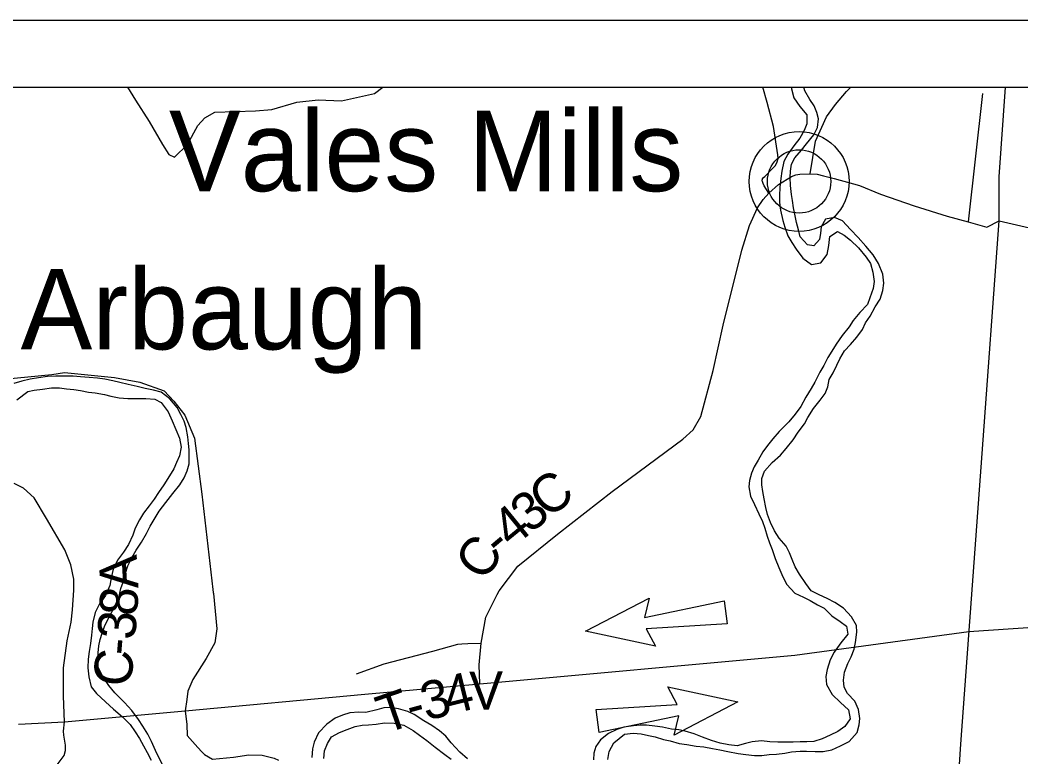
# Model space of a CAD drawing. Extents: x -15 to 405, y -40 to 87.
# Drawn here: x 26.107 to 27.6, y -28.194 to -27.096 of the extents above; entities that cross this region are included whole.
import ezdxf

# ---------------------------------------------------------------- set-up
doc = ezdxf.new("R2010")
doc.units = 0
for name, color, linetype in [('GM_P_State_Location', 7, 'Continuous'), ('GM_X_Major_Lake_Text', 7, 'Continuous'), ('GM_X_Minor_Lake', 7, 'Continuous'), ('GM_X_Minor_River', 7, 'Continuous'), ('GM_X_Rail_Line', 7, 'Continuous'), ('GM_X_State_Location', 7, 'Continuous'), ('GM_X_Township', 7, 'Continuous'), ('GM_X_Township_Road', 7, 'Continuous'), ('GM_X_Township_ROW', 7, 'Continuous'), ('GM_X_Township_Subdivision_Text', 7, 'Continuous'), ('GM_X_Township_Text', 7, 'Continuous')]:
    doc.layers.add(name, color=color, linetype=linetype)

msp = doc.modelspace()

# ---------------------------------------------------------------- linework, layer by layer
at = {"layer": 'GM_P_State_Location'}
for points in [[(26.2674, -27.1955), (26.2795, -27.2151), (26.2997, -27.2469), (26.3196, -27.2809), (26.3291, -27.2961), (26.3374, -27.2998), (26.3567, -27.2808), (26.3725, -27.2527), (26.3827, -27.2413), (26.3975, -27.233), (26.4581, -27.2306), (26.4827, -27.229), (26.5198, -27.2179), (26.5517, -27.2144), (26.5865, -27.2158), (26.6358, -27.2051), (26.6482, -27.1955)], [(27.5424, -27.2051), (27.521, -27.3963)], [(26.6091, -28.0702), (26.65, -28.055), (26.7227, -28.0362), (26.7602, -28.0259), (26.766, -28.0254)], [(26.766, -28.0254), (26.7661, -28.0254), (26.775, -28.0247), (26.7949, -28.0243)], [(26.3533, -28.1249), (26.3559, -28.1456), (26.3563, -28.1619), (26.3723, -28.1797), (26.3782, -28.186), (26.3783, -28.1861)], [(26.3783, -28.1861), (26.3821, -28.1901), (26.394, -28.1971), (26.4255, -28.1944), (26.4482, -28.1908), (26.4683, -28.1911), (26.4863, -28.1956), (26.4927, -28.1984)]]:
    msp.add_lwpolyline(points, dxfattribs=at)
at = {"layer": 'GM_X_Major_Lake_Text'}
msp.add_lwpolyline([(27.2854, -27.3245), (27.2931, -27.2763), (27.3097, -27.2399), (27.3229, -27.2216), (27.3395, -27.2018), (27.3458, -27.1955)], dxfattribs=at)
at = {"layer": 'GM_X_Rail_Line'}
for p, q in [((27.567, -27.3293), (27.5764, -27.1955)), ((27.567, -27.3948), (27.567, -27.3293)), ((27.5416, -27.7418), (27.567, -27.3948)), ((27.5098, -28.1749), (27.5416, -27.7418)), ((27.4737, -28.7166), (27.5098, -28.1749))]:
    msp.add_line(p, q, dxfattribs=at)
at = {"layer": 'GM_X_State_Location'}
for p, q in [((26.9502, -28.0065), (27.0452, -27.9573)), ((27.0452, -27.9573), (27.0384, -27.9858)), ((27.0384, -27.9858), (27.157, -27.9613)), ((27.157, -27.9613), (27.1616, -27.9954)), ((27.1616, -27.9954), (27.0406, -28.0031)), ((27.0548, -28.0289), (26.9502, -28.0065)), ((27.0406, -28.0031), (27.0548, -28.0289)), ((27.0869, -28.1155), (27.0729, -28.0895)), ((27.0729, -28.0895), (27.1775, -28.1118)), ((26.966, -28.1231), (27.0869, -28.1155)), ((27.1775, -28.1118), (27.0825, -28.1612)), ((26.9706, -28.1573), (26.966, -28.1231)), ((27.0893, -28.1327), (26.9706, -28.1573)), ((27.0825, -28.1612), (27.0893, -28.1327))]:
    msp.add_line(p, q, dxfattribs=at)
for points in [[(27.5221, -28.0069), (27.794, -27.9884), (27.8248, -27.9846), (27.9313, -27.9711), (28.0014, -27.9502), (28.0572, -27.9216), (28.1015, -27.8881), (28.1837, -27.8185), (28.3618, -27.6615), (28.4315, -27.6071), (28.5024, -27.5572), (28.767, -27.3945)], [(26.1048, -28.1452), (26.1735, -28.1414), (26.3533, -28.1249), (26.6213, -28.1005), (26.793, -28.0849), (27.2624, -28.0421), (27.5221, -28.0069)]]:
    msp.add_lwpolyline(points, dxfattribs=at)
at = {"layer": 'GM_X_Township'}
for p, q in [((23.0652, -27.0955), (30.0652, -27.0955)), ((23.1652, -27.1955), (29.9652, -27.1955))]:
    msp.add_line(p, q, dxfattribs=at)
at = {"layer": 'GM_X_Township_Road'}
for points in [[(27.2571, -27.1955), (27.2574, -27.1982), (27.2608, -27.2115), (27.2699, -27.2244), (27.2802, -27.2369), (27.2802, -27.2502), (27.2764, -27.2604), (27.2699, -27.2714), (27.2608, -27.2828), (27.252, -27.2953), (27.2463, -27.3063), (27.2429, -27.3207), (27.2414, -27.3317)], [(27.2577, -27.3553), (27.2562, -27.342), (27.2554, -27.3302), (27.2558, -27.3207), (27.2577, -27.3105), (27.2623, -27.301), (27.2725, -27.2896), (27.2798, -27.2801), (27.2908, -27.2665), (27.2961, -27.2555), (27.298, -27.2426), (27.2954, -27.2331), (27.2912, -27.2236), (27.2848, -27.2141), (27.2776, -27.2008), (27.2761, -27.1955)], [(27.2414, -27.3317), (27.2402, -27.3446), (27.2398, -27.3575), (27.2398, -27.3674), (27.2409, -27.3788), (27.2447, -27.3943), (27.2477, -27.4042), (27.2519, -27.4171), (27.258, -27.427), (27.2644, -27.4368), (27.2746, -27.4505), (27.2875, -27.46), (27.3012, -27.4574), (27.3107, -27.4452), (27.313, -27.4316), (27.3145, -27.4183), (27.3263, -27.4107), (27.3358, -27.4164), (27.3457, -27.4236), (27.3574, -27.435), (27.3688, -27.4487), (27.3753, -27.4586), (27.3787, -27.4715), (27.3809, -27.4851), (27.3794, -27.4957), (27.3741, -27.5094), (27.3706, -27.5196), (27.3596, -27.5314), (27.3493, -27.5435), (27.3433, -27.553), (27.333, -27.5659), (27.3243, -27.5784), (27.3178, -27.589), (27.3117, -27.5985), (27.3056, -27.6103), (27.2999, -27.6205), (27.2923, -27.6353), (27.2866, -27.6448), (27.279, -27.6577), (27.2714, -27.6713), (27.263, -27.6827), (27.2535, -27.6945), (27.2391, -27.7089), (27.2299, -27.7195), (27.2216, -27.7297), (27.2147, -27.7392), (27.2079, -27.7517), (27.2018, -27.7616), (27.198, -27.7711), (27.1949, -27.7817), (27.1938, -27.7912), (27.1964, -27.8052), (27.2021, -27.8178), (27.2086, -27.8314), (27.2142, -27.8428), (27.2176, -27.8527), (27.2214, -27.8648), (27.2248, -27.8747), (27.2286, -27.8849), (27.2332, -27.8982), (27.2385, -27.9115), (27.2445, -27.9256), (27.2506, -27.937), (27.2627, -27.9495), (27.2756, -27.9556), (27.2855, -27.9605), (27.2965, -27.967), (27.306, -27.9723), (27.3178, -27.9837), (27.3299, -27.992), (27.3394, -27.9989), (27.3413, -28.011), (27.331, -28.0239), (27.3211, -28.0376), (27.315, -28.0493), (27.3105, -28.0634), (27.3089, -28.074), (27.3097, -28.0861), (27.318, -28.1009), (27.3305, -28.1127), (27.3423, -28.1237), (27.3449, -28.137), (27.3369, -28.1484), (27.3267, -28.156), (27.3153, -28.1616), (27.3031, -28.1666), (27.2906, -28.1707), (27.2803, -28.1711), (27.2705, -28.1715), (27.2602, -28.1719), (27.2371, -28.1718), (27.2253, -28.1711), (27.2128, -28.1699), (27.1991, -28.1714), (27.1888, -28.1737), (27.1767, -28.1771), (27.1642, -28.1756), (27.1512, -28.1733), (27.138, -28.1691), (27.1247, -28.1645), (27.1125, -28.1596)], [(27.1395, -28.1813), (27.1505, -28.1832), (27.1626, -28.1858), (27.1782, -28.1889), (27.1892, -28.1904), (27.2021, -28.1915), (27.2131, -28.1919), (27.2241, -28.1904), (27.2351, -28.1897), (27.2477, -28.1882), (27.2576, -28.1863), (27.2705, -28.1851), (27.28, -28.1852), (27.2929, -28.1859), (27.3046, -28.1855), (27.3175, -28.1833), (27.3308, -28.1772), (27.3434, -28.1708), (27.3552, -28.1575), (27.3582, -28.1461), (27.3594, -28.1363), (27.3575, -28.1233), (27.3518, -28.1108), (27.3408, -28.0994), (27.3359, -28.0899), (27.3351, -28.0793), (27.3363, -28.0676), (27.3416, -28.0547), (27.3465, -28.0444), (27.3507, -28.0334), (27.353, -28.0232), (27.3549, -28.008), (27.3546, -27.9977), (27.347, -27.9848), (27.3352, -27.9723), (27.322, -27.9636), (27.3109, -27.9575), (27.2988, -27.9522), (27.2867, -27.9461), (27.2787, -27.9355), (27.2696, -27.9214), (27.2631, -27.9104), (27.2586, -27.8998), (27.2544, -27.8895), (27.2495, -27.8797), (27.2389, -27.8679), (27.2321, -27.8569), (27.226, -27.8443), (27.2218, -27.8326), (27.2192, -27.8223), (27.2166, -27.809), (27.215, -27.798), (27.2135, -27.7882), (27.2132, -27.7787), (27.217, -27.7677), (27.2288, -27.7552), (27.2409, -27.7442), (27.2497, -27.7343), (27.2599, -27.721), (27.2672, -27.71), (27.277, -27.6972), (27.282, -27.6877), (27.2904, -27.6744), (27.3002, -27.6623), (27.3078, -27.652), (27.3117, -27.6422), (27.3139, -27.6312), (27.3196, -27.6213), (27.325, -27.6099), (27.3295, -27.6004), (27.3364, -27.5887), (27.3455, -27.5792), (27.355, -27.5682), (27.3634, -27.5568), (27.368, -27.547), (27.3748, -27.5371), (27.3824, -27.5231), (27.3896, -27.5117), (27.3938, -27.4988), (27.395, -27.4878), (27.3938, -27.4741), (27.3874, -27.4582), (27.3791, -27.4457), (27.3681, -27.4324), (27.3567, -27.4198), (27.3457, -27.4077), (27.3336, -27.3948), (27.3214, -27.3898), (27.3081, -27.3921), (27.3017, -27.4035), (27.3009, -27.413), (27.2994, -27.4225), (27.291, -27.4323), (27.2815, -27.4308), (27.2705, -27.4186), (27.2679, -27.408), (27.2648, -27.3974), (27.2626, -27.3849), (27.2607, -27.3754), (27.2588, -27.3647), (27.2577, -27.3553)], [(26.3565, -27.7674), (26.3596, -27.7572), (26.3596, -27.7477), (26.3592, -27.7363), (26.3585, -27.7268), (26.3574, -27.7166), (26.3547, -27.7029), (26.3517, -27.6934), (26.3471, -27.6832), (26.3414, -27.6729), (26.3305, -27.66), (26.3175, -27.6501), (26.3062, -27.6471), (26.294, -27.6448), (26.2819, -27.6418), (26.2686, -27.6387), (26.2561, -27.6357), (26.2458, -27.6334), (26.2337, -27.6307), (26.2226, -27.6292), (26.2105, -27.6284), (26.1972, -27.6273), (26.1862, -27.6265), (26.1608, -27.6265), (26.1482, -27.6269), (26.1349, -27.6287), (26.1224, -27.631), (26.1099, -27.634), (26.0981, -27.6374)], [(26.1026, -27.6614), (26.1186, -27.6492), (26.1281, -27.6473), (26.1406, -27.6458), (26.1543, -27.6439), (26.1661, -27.6436), (26.1763, -27.6451), (26.1873, -27.6462), (26.1972, -27.6478), (26.2093, -27.6501), (26.2192, -27.6512), (26.2329, -27.6535), (26.2427, -27.6561), (26.2549, -27.6588), (26.2678, -27.6596), (26.2948, -27.6596), (26.308, -27.6608), (26.3175, -27.6657), (26.3282, -27.6794), (26.3342, -27.693), (26.3395, -27.7059), (26.3452, -27.7185), (26.3475, -27.7321), (26.3452, -27.745), (26.3406, -27.7549), (26.3364, -27.7644), (26.3277, -27.7788)], [(26.32, -28.2068), (26.3094, -28.184), (26.303, -28.1708), (26.298, -28.1597), (26.2905, -28.148), (26.284, -28.1381), (26.2738, -28.1244), (26.2632, -28.1127), (26.2484, -28.0982), (26.2396, -28.0876), (26.2302, -28.0732), (26.2237, -28.0599), (26.2233, -28.0485), (26.2237, -28.0386), (26.2249, -28.0284), (26.2268, -28.0189), (26.2298, -28.0094), (26.2329, -27.9996), (26.2386, -27.9878), (26.2439, -27.9779), (26.2496, -27.9669), (26.255, -27.9544), (26.2576, -27.943), (26.2611, -27.9335), (26.2641, -27.9214), (26.2679, -27.9089), (26.2744, -27.896), (26.2805, -27.8857), (26.2881, -27.8736), (26.2957, -27.8607), (26.301, -27.8501), (26.3147, -27.8273), (26.3246, -27.8144), (26.3349, -27.8012), (26.3455, -27.7883), (26.352, -27.778), (26.3565, -27.7674)], [(26.3277, -27.7788), (26.3216, -27.7883), (26.3136, -27.7996), (26.3071, -27.8095), (26.2999, -27.8194), (26.2915, -27.8304), (26.2855, -27.8402), (26.279, -27.8531), (26.2752, -27.8634), (26.2687, -27.8774), (26.2615, -27.8888), (26.2524, -27.9005), (26.2459, -27.9142), (26.2432, -27.9271), (26.2409, -27.9381), (26.2348, -27.9533), (26.2253, -27.9665), (26.2192, -27.9787), (26.2158, -27.9931), (26.2147, -28.0026), (26.2139, -28.0121), (26.2124, -28.025), (26.2105, -28.0367), (26.2089, -28.0481), (26.2085, -28.061), (26.2097, -28.0743), (26.2134, -28.0891), (26.2214, -28.0993), (26.2347, -28.1115), (26.2468, -28.1225), (26.2601, -28.1343), (26.2715, -28.1457), (26.2787, -28.1563), (26.2851, -28.1662), (26.2912, -28.1772), (26.2969, -28.1874), (26.3026, -28.1988)], [(26.7745, -28.1965), (26.7628, -28.1867), (26.7499, -28.1726), (26.7419, -28.1627), (26.7324, -28.1548), (26.7211, -28.1472), (26.7093, -28.1399), (26.6949, -28.1308), (26.6854, -28.1263), (26.6717, -28.1221), (26.66, -28.1202), (26.6497, -28.1205), (26.6391, -28.1236), (26.6227, -28.1274), (26.6125, -28.1273), (26.5988, -28.1281), (26.5878, -28.1315), (26.5772, -28.136), (26.5646, -28.1448), (26.5521, -28.158), (26.5456, -28.1717), (26.5433, -28.1819), (26.5425, -28.1945)], [(26.56, -28.1964), (26.5612, -28.1846), (26.5657, -28.1736), (26.5718, -28.1641), (26.5836, -28.1573), (26.595, -28.1531), (26.6068, -28.1486), (26.6174, -28.1467), (26.6269, -28.146), (26.6383, -28.1448), (26.6508, -28.1429), (26.6649, -28.1433), (26.6793, -28.1464), (26.6933, -28.1544), (26.7028, -28.1616), (26.7138, -28.1695), (26.726, -28.1794), (26.7408, -28.1901), (26.7502, -28.1973)], [(27.1125, -28.1596), (27.0992, -28.1554), (27.0894, -28.1535), (27.0787, -28.1524), (27.0651, -28.1493), (27.0537, -28.1478), (27.0415, -28.1466), (27.0317, -28.1466), (27.0218, -28.1474), (27.0074, -28.1493), (26.9971, -28.1527), (26.9846, -28.1587), (26.9728, -28.1682), (26.9659, -28.1785), (26.9629, -28.1883), (26.9625, -28.1982)], [(26.9838, -28.1975), (26.9857, -28.1857), (26.9925, -28.1728), (27.0085, -28.1599), (27.0214, -28.1584), (27.0332, -28.1595), (27.0442, -28.1618), (27.0544, -28.1641), (27.0666, -28.1679), (27.0764, -28.1698), (27.0901, -28.174), (27.1015, -28.1755), (27.1155, -28.1778), (27.1269, -28.179), (27.1395, -28.1813)]]:
    msp.add_lwpolyline(points, dxfattribs=at)
at = {"layer": 'GM_X_Township_Subdivision_Text'}
for radius in [0.0744, 0.0472]:
    msp.add_circle((27.2689, -27.3361), radius, dxfattribs=at)
at = {"layer": 'GM_X_Township_Text'}
for points in [[(27.2321, -27.3136), (27.2334, -27.3121), (27.2361, -27.3071), (27.2374, -27.3019), (27.2372, -27.2965), (27.2306, -27.2544), (27.2214, -27.2184), (27.2148, -27.1955)], [(27.2238, -27.3537), (27.2169, -27.3428), (27.2151, -27.3391), (27.2141, -27.3364), (27.2139, -27.3352), (27.2139, -27.334), (27.2141, -27.3329), (27.2145, -27.332), (27.2157, -27.3304), (27.2175, -27.3286), (27.2289, -27.3173), (27.2321, -27.3136)], [(27.2238, -27.3537), (27.2381, -27.3408), (27.2574, -27.3286), (27.2639, -27.3264), (27.27, -27.3252), (27.2854, -27.3245), (27.2956, -27.3254), (27.3054, -27.3276), (27.3211, -27.3319), (27.3587, -27.342), (27.3902, -27.3548), (27.4402, -27.3725), (27.4896, -27.3876), (27.521, -27.3963), (27.5488, -27.4041), (27.567, -27.3948)], [(26.8185, -27.9519), (26.8214, -27.9461), (26.8496, -27.9096), (26.9086, -27.8617), (26.9903, -27.7982), (27.0954, -27.7203), (27.1109, -27.7062), (27.1222, -27.6864), (27.1409, -27.6178), (27.1554, -27.5503), (27.1835, -27.4384), (27.1951, -27.4016), (27.2068, -27.3754), (27.2151, -27.3632), (27.2238, -27.3537)], [(27.567, -27.3948), (27.6319, -27.4097), (27.6698, -27.4189), (27.702, -27.4333), (27.7252, -27.4543), (27.751, -27.4717), (27.7886, -27.4895), (27.8171, -27.4952), (27.854, -27.4914), (27.9356, -27.4845), (27.9967, -27.4852), (28.0545, -27.4932), (28.1213, -27.5186), (28.187, -27.5402), (28.2577, -27.553), (28.3302, -27.5629), (28.372, -27.5629), (28.4073, -27.5541), (28.4164, -27.5499)], [(26.0829, -27.6306), (26.1547, -27.624), (26.1736, -27.6209), (26.2479, -27.6283), (26.2859, -27.6351), (26.3219, -27.6482), (26.3367, -27.6634), (26.3531, -27.6842), (26.3673, -27.7186), (26.3785, -27.8024), (26.3949, -27.9445), (26.3953, -27.9485), (26.3955, -27.9503)], [(26.1735, -28.1414), (26.1719, -28.1034), (26.1721, -28.0609), (26.1776, -28.021), (26.1833, -27.9928), (26.1852, -27.9745), (26.1872, -27.9454), (26.1874, -27.9288), (26.1831, -27.9074), (26.174, -27.8853), (26.1465, -27.8386), (26.1285, -27.8074), (26.1126, -27.793), (26.0986, -27.7864)], [(26.3955, -27.9503), (26.4004, -28.0029), (26.3975, -28.0237), (26.3847, -28.0473), (26.365, -28.0784), (26.3575, -28.0959), (26.3561, -28.1084), (26.3533, -28.1249)], [(26.793, -28.0849), (26.7918, -28.0565), (26.7949, -28.0243), (26.8017, -27.9856), (26.8185, -27.9519)], [(26.175, -28.1817), (26.1751, -28.1763), (26.1724, -28.1615), (26.1722, -28.1555), (26.1735, -28.1414)], [(26.1393, -28.3413), (26.1279, -28.3266), (26.1217, -28.3118), (26.1198, -28.2928), (26.119, -28.2784), (26.1212, -28.2602), (26.1295, -28.245), (26.1389, -28.231), (26.1502, -28.2181), (26.1627, -28.2055), (26.1729, -28.1919), (26.175, -28.1844), (26.175, -28.1817)]]:
    msp.add_lwpolyline(points, dxfattribs=at)

# ---------------------------------------------------------------- texts
at = {"layer": 'GM_X_Minor_Lake'}
for s, rotation, p in [('C', 38.5172, (26.8948, -27.8401)), ('3', 38.6687, (26.8675, -27.8619)), ('4', 39.1979, (26.8405, -27.884)), ('C', 54.7336, (26.7985, -27.9342)), ('-', 40.2973, (26.8229, -27.8989)), ('A', 93.0955, (26.2838, -27.9422)), ('8', 86.2211, (26.2815, -27.9845)), ('3', 85.4109, (26.2786, -28.0203)), ('-', 85.1912, (26.2766, -28.0438)), ('C', 85.131, (26.2727, -28.0903))]:
    msp.add_text(s, height=0.0568, rotation=rotation, dxfattribs=at).set_placement(p)
at = {"layer": 'GM_X_Minor_River'}
for s, rotation, p in [('4', 14.0034, (26.7467, -28.1315)), ('V', 0.4189, (26.7771, -28.1235)), ('3', 14.4527, (26.7129, -28.1402)), ('T', 19.1384, (26.6514, -28.1599)), ('-', 15.1798, (26.6906, -28.1463))]:
    msp.add_text(s, height=0.0568, rotation=rotation, dxfattribs=at).set_placement(p)
at = {"layer": 'GM_X_Township_ROW'}
for s, p in [('Vales Mills', (26.3292, -27.3506)), ('Arbaugh', (26.108, -27.5864))]:
    msp.add_text(s, height=0.12, rotation=0, dxfattribs=at).set_placement(p)

doc.saveas('drawing.dxf')
